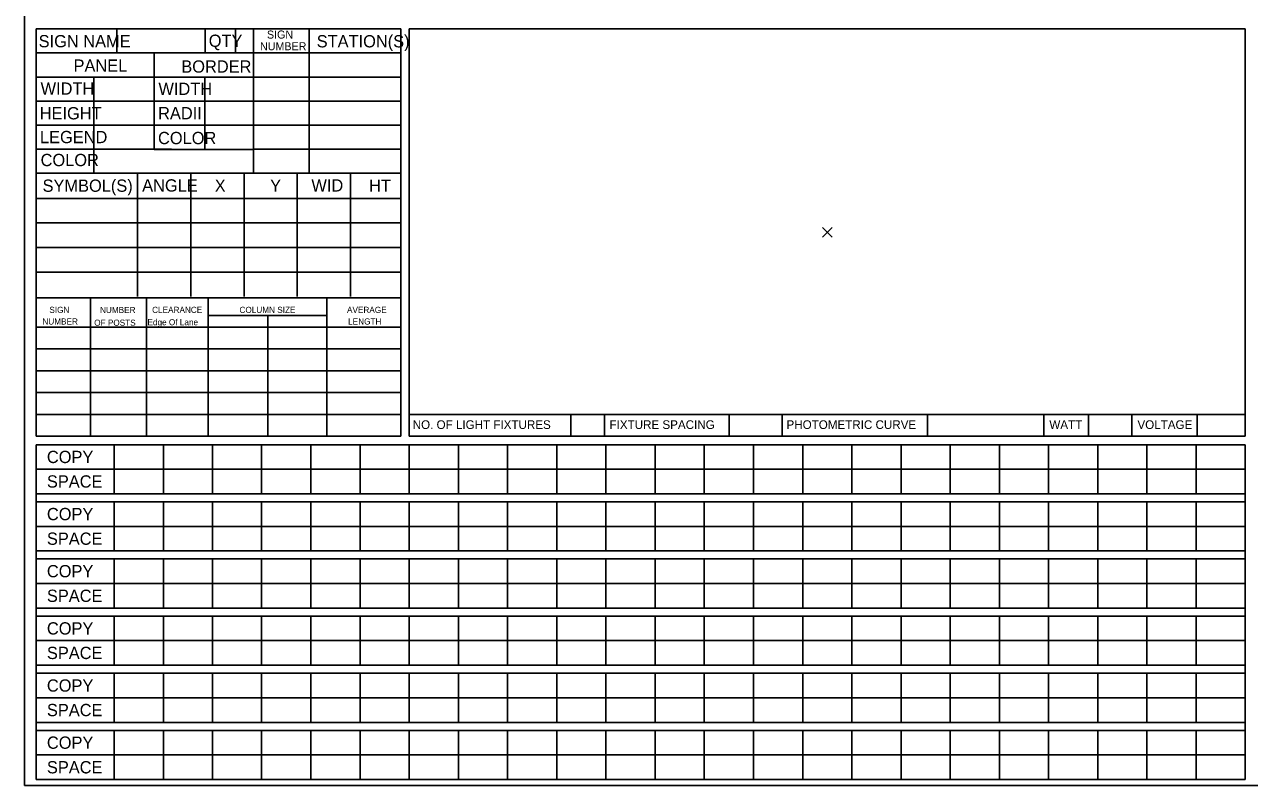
# Model space of a CAD drawing. Extents: x -875 to -645, y -2221 to -2162.
# Drawn here: x -781.19 to -766.2, y -2220.45 to -2211.14 of the extents above; entities that cross this region are included whole.
import ezdxf

# ---------------------------------------------------------------- set-up
doc = ezdxf.new("R2010")
doc.units = 0
for name, color, linetype in [('NonPlottingEle_dp', 7, 'Continuous'), ('SheetLinesMisc2_dp', 7, 'Continuous'), ('TextMinor', 7, 'Continuous')]:
    doc.layers.add(name, color=color, linetype=linetype)

msp = doc.modelspace()

# ---------------------------------------------------------------- linework, layer by layer
at = {"layer": 'NonPlottingEle_dp'}
for p, q in [((-771.421, -2213.619), (-771.305, -2213.736)), ((-771.421, -2213.736), (-771.305, -2213.619))]:
    msp.add_line(p, q, dxfattribs=at)
at = {"layer": 'SheetLinesMisc2_dp'}
for p, q in [((-781.188, -2201.717), (-781.188, -2220.446)), ((-781.044, -2216.173), (-781.044, -2211.189)), ((-781.044, -2211.189), (-776.583, -2211.189)), ((-780.06, -2211.189), (-780.06, -2211.483)), ((-778.976, -2211.189), (-778.976, -2211.483)), ((-778.606, -2211.189), (-778.606, -2211.483)), ((-778.385, -2211.189), (-778.385, -2212.955)), ((-777.706, -2211.189), (-777.706, -2212.955)), ((-776.583, -2211.189), (-776.583, -2216.173)), ((-776.48, -2211.189), (-766.247, -2211.189)), ((-776.48, -2211.189), (-776.48, -2216.166)), ((-766.247, -2216.166), (-766.247, -2211.189)), ((-781.044, -2211.483), (-776.583, -2211.483)), ((-779.602, -2211.483), (-779.602, -2212.664)), ((-781.044, -2211.778), (-776.583, -2211.778)), ((-780.339, -2211.778), (-780.339, -2212.955)), ((-778.98, -2211.781), (-778.98, -2212.664)), ((-781.044, -2212.072), (-776.583, -2212.072)), ((-781.044, -2212.367), (-776.583, -2212.367)), ((-781.044, -2212.661), (-779.389, -2212.661)), ((-779.602, -2212.664), (-778.385, -2212.664)), ((-778.385, -2212.661), (-776.583, -2212.661)), ((-781.044, -2212.955), (-776.583, -2212.955)), ((-779.805, -2212.961), (-779.805, -2214.464)), ((-779.153, -2212.961), (-779.153, -2214.464)), ((-778.501, -2212.961), (-778.501, -2214.464)), ((-777.849, -2212.961), (-777.849, -2214.464)), ((-777.197, -2212.961), (-777.197, -2214.464)), ((-781.043, -2213.262), (-776.583, -2213.262)), ((-781.043, -2213.563), (-776.583, -2213.563)), ((-781.043, -2213.863), (-776.583, -2213.863)), ((-781.043, -2214.164), (-776.583, -2214.164)), ((-781.044, -2214.479), (-776.583, -2214.479)), ((-780.382, -2214.479), (-780.382, -2216.173)), ((-779.697, -2214.479), (-779.697, -2216.173)), ((-778.942, -2214.479), (-778.942, -2216.173)), ((-777.487, -2214.479), (-777.487, -2216.173)), ((-778.942, -2214.694), (-777.488, -2214.694)), ((-778.212, -2214.694), (-778.212, -2216.173)), ((-781.044, -2214.838), (-776.583, -2214.838)), ((-781.044, -2215.105), (-776.583, -2215.105)), ((-781.044, -2215.372), (-776.583, -2215.372)), ((-781.044, -2215.639), (-776.583, -2215.639)), ((-781.044, -2215.906), (-776.583, -2215.906)), ((-776.48, -2215.906), (-766.247, -2215.906)), ((-774.503, -2215.906), (-774.503, -2216.173)), ((-774.089, -2215.906), (-774.089, -2216.173)), ((-772.565, -2215.906), (-772.565, -2216.173)), ((-771.917, -2215.906), (-771.917, -2216.173)), ((-770.135, -2215.906), (-770.135, -2216.173)), ((-768.713, -2215.906), (-768.713, -2216.173)), ((-768.164, -2215.906), (-768.164, -2216.173)), ((-767.635, -2215.906), (-767.635, -2216.173)), ((-766.838, -2215.906), (-766.838, -2216.173)), ((-781.044, -2216.173), (-776.583, -2216.173)), ((-776.48, -2216.166), (-776.48, -2216.173)), ((-776.48, -2216.173), (-766.247, -2216.173)), ((-766.247, -2216.173), (-766.247, -2216.166)), ((-781.044, -2216.276), (-766.247, -2216.276)), ((-781.044, -2220.373), (-781.044, -2216.276)), ((-780.091, -2216.276), (-780.091, -2216.877)), ((-779.489, -2216.276), (-779.489, -2216.877)), ((-778.887, -2216.276), (-778.887, -2216.877)), ((-778.286, -2216.276), (-778.286, -2216.877)), ((-777.684, -2216.276), (-777.684, -2216.877)), ((-777.082, -2216.276), (-777.082, -2216.877)), ((-776.48, -2216.276), (-776.48, -2216.877)), ((-775.878, -2216.276), (-775.878, -2216.877)), ((-775.276, -2216.276), (-775.276, -2216.877)), ((-774.674, -2216.276), (-774.674, -2216.877)), ((-774.072, -2216.276), (-774.072, -2216.877)), ((-773.47, -2216.276), (-773.47, -2216.877)), ((-772.868, -2216.276), (-772.868, -2216.877)), ((-772.266, -2216.276), (-772.266, -2216.877)), ((-771.664, -2216.276), (-771.664, -2216.877)), ((-771.062, -2216.276), (-771.062, -2216.877)), ((-770.46, -2216.276), (-770.46, -2216.877)), ((-769.858, -2216.276), (-769.858, -2216.877)), ((-769.256, -2216.276), (-769.256, -2216.877)), ((-768.654, -2216.276), (-768.654, -2216.877)), ((-768.053, -2216.276), (-768.053, -2216.877)), ((-767.451, -2216.276), (-767.451, -2216.877)), ((-766.849, -2216.276), (-766.849, -2216.877)), ((-766.247, -2220.373), (-766.247, -2216.276)), ((-781.044, -2216.576), (-766.247, -2216.576)), ((-781.044, -2216.877), (-766.247, -2216.877)), ((-781.044, -2216.975), (-766.247, -2216.975)), ((-780.091, -2216.975), (-780.091, -2217.576)), ((-779.489, -2216.975), (-779.489, -2217.576)), ((-778.887, -2216.975), (-778.887, -2217.576)), ((-778.286, -2216.975), (-778.286, -2217.576)), ((-777.684, -2216.975), (-777.684, -2217.576)), ((-777.082, -2216.975), (-777.082, -2217.576)), ((-776.48, -2216.975), (-776.48, -2217.576)), ((-775.878, -2216.975), (-775.878, -2217.576)), ((-775.276, -2216.975), (-775.276, -2217.576)), ((-774.674, -2216.975), (-774.674, -2217.576)), ((-774.072, -2216.975), (-774.072, -2217.576)), ((-773.47, -2216.975), (-773.47, -2217.576)), ((-772.868, -2216.975), (-772.868, -2217.576)), ((-772.266, -2216.975), (-772.266, -2217.576)), ((-771.664, -2216.975), (-771.664, -2217.576)), ((-771.062, -2216.975), (-771.062, -2217.576)), ((-770.46, -2216.975), (-770.46, -2217.576)), ((-769.858, -2216.975), (-769.858, -2217.576)), ((-769.256, -2216.975), (-769.256, -2217.576)), ((-768.654, -2216.975), (-768.654, -2217.576)), ((-768.053, -2216.975), (-768.053, -2217.576)), ((-767.451, -2216.975), (-767.451, -2217.576)), ((-766.849, -2216.975), (-766.849, -2217.576)), ((-781.044, -2217.276), (-766.247, -2217.276)), ((-781.044, -2217.576), (-766.247, -2217.576)), ((-781.044, -2217.674), (-766.247, -2217.674)), ((-780.091, -2217.674), (-780.091, -2218.276)), ((-779.489, -2217.674), (-779.489, -2218.276)), ((-778.887, -2217.674), (-778.887, -2218.276)), ((-778.286, -2217.674), (-778.286, -2218.276)), ((-777.684, -2217.674), (-777.684, -2218.276)), ((-777.082, -2217.674), (-777.082, -2218.276)), ((-776.48, -2217.674), (-776.48, -2218.276)), ((-775.878, -2217.674), (-775.878, -2218.276)), ((-775.276, -2217.674), (-775.276, -2218.276)), ((-774.674, -2217.674), (-774.674, -2218.276)), ((-774.072, -2217.674), (-774.072, -2218.276)), ((-773.47, -2217.674), (-773.47, -2218.276)), ((-772.868, -2217.674), (-772.868, -2218.276)), ((-772.266, -2217.674), (-772.266, -2218.276)), ((-771.664, -2217.674), (-771.664, -2218.276)), ((-771.062, -2217.674), (-771.062, -2218.276)), ((-770.46, -2217.674), (-770.46, -2218.276)), ((-769.858, -2217.674), (-769.858, -2218.276)), ((-769.256, -2217.674), (-769.256, -2218.276)), ((-768.654, -2217.674), (-768.654, -2218.276)), ((-768.053, -2217.674), (-768.053, -2218.276)), ((-767.451, -2217.674), (-767.451, -2218.276)), ((-766.849, -2217.674), (-766.849, -2218.276)), ((-781.044, -2217.975), (-766.247, -2217.975)), ((-781.044, -2218.276), (-766.247, -2218.276)), ((-781.044, -2218.374), (-766.247, -2218.374)), ((-780.091, -2218.374), (-780.091, -2218.975)), ((-779.489, -2218.374), (-779.489, -2218.975)), ((-778.887, -2218.374), (-778.887, -2218.975)), ((-778.286, -2218.374), (-778.286, -2218.975)), ((-777.684, -2218.374), (-777.684, -2218.975)), ((-777.082, -2218.374), (-777.082, -2218.975)), ((-776.48, -2218.374), (-776.48, -2218.975)), ((-775.878, -2218.374), (-775.878, -2218.975)), ((-775.276, -2218.374), (-775.276, -2218.975)), ((-774.674, -2218.374), (-774.674, -2218.975)), ((-774.072, -2218.374), (-774.072, -2218.975)), ((-773.47, -2218.374), (-773.47, -2218.975)), ((-772.868, -2218.374), (-772.868, -2218.975)), ((-772.266, -2218.374), (-772.266, -2218.975)), ((-771.664, -2218.374), (-771.664, -2218.975)), ((-771.062, -2218.374), (-771.062, -2218.975)), ((-770.46, -2218.374), (-770.46, -2218.975)), ((-769.858, -2218.374), (-769.858, -2218.975)), ((-769.256, -2218.374), (-769.256, -2218.975)), ((-768.654, -2218.374), (-768.654, -2218.975)), ((-768.053, -2218.374), (-768.053, -2218.975)), ((-767.451, -2218.374), (-767.451, -2218.975)), ((-766.849, -2218.374), (-766.849, -2218.975)), ((-781.044, -2218.674), (-766.247, -2218.674)), ((-781.044, -2218.975), (-766.247, -2218.975)), ((-781.044, -2219.073), (-766.247, -2219.073)), ((-780.091, -2219.073), (-780.091, -2219.674)), ((-779.489, -2219.073), (-779.489, -2219.674)), ((-778.887, -2219.073), (-778.887, -2219.674)), ((-778.286, -2219.073), (-778.286, -2219.674)), ((-777.684, -2219.073), (-777.684, -2219.674)), ((-777.082, -2219.073), (-777.082, -2219.674)), ((-776.48, -2219.073), (-776.48, -2219.674)), ((-775.878, -2219.073), (-775.878, -2219.674)), ((-775.276, -2219.073), (-775.276, -2219.674)), ((-774.674, -2219.073), (-774.674, -2219.674)), ((-774.072, -2219.073), (-774.072, -2219.674)), ((-773.47, -2219.073), (-773.47, -2219.674)), ((-772.868, -2219.073), (-772.868, -2219.674)), ((-772.266, -2219.073), (-772.266, -2219.674)), ((-771.664, -2219.073), (-771.664, -2219.674)), ((-771.062, -2219.073), (-771.062, -2219.674)), ((-770.46, -2219.073), (-770.46, -2219.674)), ((-769.858, -2219.073), (-769.858, -2219.674)), ((-769.256, -2219.073), (-769.256, -2219.674)), ((-768.654, -2219.073), (-768.654, -2219.674)), ((-768.053, -2219.073), (-768.053, -2219.674)), ((-767.451, -2219.073), (-767.451, -2219.674)), ((-766.849, -2219.073), (-766.849, -2219.674)), ((-781.044, -2219.374), (-766.247, -2219.374)), ((-781.044, -2219.674), (-766.247, -2219.674)), ((-781.044, -2219.772), (-766.247, -2219.772)), ((-780.091, -2219.772), (-780.091, -2220.373)), ((-779.489, -2219.772), (-779.489, -2220.373)), ((-778.887, -2219.772), (-778.887, -2220.373)), ((-778.286, -2219.772), (-778.286, -2220.373)), ((-777.684, -2219.772), (-777.684, -2220.373)), ((-777.082, -2219.772), (-777.082, -2220.373)), ((-776.48, -2219.772), (-776.48, -2220.373)), ((-775.878, -2219.772), (-775.878, -2220.373)), ((-775.276, -2219.772), (-775.276, -2220.373)), ((-774.674, -2219.772), (-774.674, -2220.373)), ((-774.072, -2219.772), (-774.072, -2220.373)), ((-773.47, -2219.772), (-773.47, -2220.373)), ((-772.868, -2219.772), (-772.868, -2220.373)), ((-772.266, -2219.772), (-772.266, -2220.373)), ((-771.664, -2219.772), (-771.664, -2220.373)), ((-771.062, -2219.772), (-771.062, -2220.373)), ((-770.46, -2219.772), (-770.46, -2220.373)), ((-769.858, -2219.772), (-769.858, -2220.373)), ((-769.256, -2219.772), (-769.256, -2220.373)), ((-768.654, -2219.772), (-768.654, -2220.373)), ((-768.053, -2219.772), (-768.053, -2220.373)), ((-767.451, -2219.772), (-767.451, -2220.373)), ((-766.849, -2219.772), (-766.849, -2220.373)), ((-781.044, -2220.073), (-766.247, -2220.073)), ((-781.044, -2220.373), (-766.247, -2220.373)), ((-781.188, -2220.446), (-751.101, -2220.446))]:
    msp.add_line(p, q, dxfattribs=at)

# ---------------------------------------------------------------- texts
at = {"layer": 'TextMinor'}
for s, height, p in [('SIGN NAME', 0.15, (-781.015, -2211.414)), ('QTY', 0.15, (-778.933, -2211.409)), ('SIGN', 0.098, (-778.221, -2211.307)), ('STATION(S)', 0.15, (-777.612, -2211.415)), ('NUMBER', 0.098, (-778.306, -2211.45)), ('PANEL', 0.15, (-780.588, -2211.713)), ('BORDER', 0.15, (-779.269, -2211.724)), ('WIDTH', 0.15, (-780.991, -2211.994)), ('WIDTH', 0.15, (-779.549, -2211.997)), ('HEIGHT', 0.15, (-781.002, -2212.296)), ('RADII', 0.15, (-779.553, -2212.295)), ('LEGEND', 0.15, (-780.999, -2212.587)), ('COLOR', 0.15, (-779.554, -2212.599)), ('COLOR', 0.15, (-780.991, -2212.868)), ('SYMBOL(S)', 0.15, (-780.967, -2213.182)), ('ANGLE', 0.15, (-779.748, -2213.179)), ('X', 0.15, (-778.86, -2213.182)), ('Y', 0.15, (-778.182, -2213.182)), ('WID', 0.15, (-777.677, -2213.179)), ('HT', 0.15, (-776.971, -2213.182)), ('SIGN', 0.075, (-780.884, -2214.664)), ('NUMBER', 0.075, (-780.264, -2214.665)), ('CLEARANCE', 0.075, (-779.626, -2214.664)), ('COLUMN SIZE', 0.07499, (-778.557, -2214.664)), ('AVERAGE', 0.075, (-777.241, -2214.664)), ('NUMBER', 0.075, (-780.969, -2214.806)), ('OF POSTS', 0.075, (-780.335, -2214.821)), ('Edge Of Lane', 0.07499, (-779.683, -2214.815)), ('LENGTH', 0.075, (-777.227, -2214.806)), ('NO. OF LIGHT FIXTURES', 0.10629, (-776.437, -2216.084)), ('FIXTURE SPACING', 0.10629, (-774.028, -2216.084)), ('PHOTOMETRIC CURVE', 0.10629, (-771.862, -2216.084)), ('WATT', 0.1063, (-768.645, -2216.084)), ('VOLTAGE', 0.1063, (-767.567, -2216.084)), ('COPY', 0.15, (-780.914, -2216.501)), ('SPACE', 0.15, (-780.914, -2216.801)), ('COPY', 0.15, (-780.914, -2217.2)), ('SPACE', 0.15, (-780.914, -2217.501)), ('COPY', 0.15, (-780.914, -2217.899)), ('SPACE', 0.15, (-780.914, -2218.2)), ('COPY', 0.15, (-780.914, -2218.599)), ('SPACE', 0.15, (-780.914, -2218.899)), ('COPY', 0.15, (-780.914, -2219.298)), ('SPACE', 0.15, (-780.914, -2219.598)), ('COPY', 0.15, (-780.914, -2219.997)), ('SPACE', 0.15, (-780.914, -2220.298))]:
    msp.add_text(s, height=height, dxfattribs=at).set_placement(p)

doc.saveas('drawing.dxf')
